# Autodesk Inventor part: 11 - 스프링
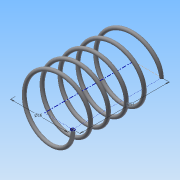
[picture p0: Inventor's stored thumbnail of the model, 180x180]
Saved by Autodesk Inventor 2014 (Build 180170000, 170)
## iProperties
Created: 2015-06
Part Number: 11 - 스프링
Material: 강철, 연강
Document SubType Name: Modeling
Designer: Administrator
Density: 7.86 g/cm^3
Appearance: 강철
Mass: 1.5292 g
Surface Area: 7.8715 cm^2
Volume: 0.194555 cm^3
Author: Administrator
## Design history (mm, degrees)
sketch "스케치1"
  geometry: L1 (0, 0)-(8, 0); L2 (8, 0)-(8, 14.5); L3 (8, 14.5)-(0, 14.5); L4 (0, 14.5)-(0, 0); C1 r 0.5 at (8, 0)
  constraints: 8 end point, 2 parallel, 1 centre point, 1 coincident, 1 horizontal, 1 perpendicular
  dimensions: "d1" = 1 diameter of C1; "d2" = 16 diameter of L2 L4; "d3" = 14.5 distance of L1.end L2.end (derived)
feature "코일1" sketch "스케치1" pitch "d4" = 10; turns "d6" = 5; dims "d5" = 14.5 (= d3), "d7" = 0, angle "d8" = 90 deg, angle "d9" = 90 deg, "d10" = 0, "d11" = 0
sketch "스케치2"
  geometry: L1 (-8.5, 0)-(-7.5, 0) reference; 1 further point
  constraints: 1 horizontal alignment
extrude "돌출1" cut sketch "스케치2" stored distance "d12" = 10; taper "d13" = 0 deg
node "작업 평면1"
sketch "스케치3"
  geometry: L1 (8.5, 0)-(7.5, 0) reference; 1 further point
  constraints: 1 horizontal alignment
extrude "돌출2" cut sketch "스케치3" stored distance "d15" = 10; taper "d16" = 0 deg
node "솔리드1"
node "절단 모서리 투영1"
node "절단 모서리 투영2"
other parameters: "d14" = -14.5 (= -d3)
